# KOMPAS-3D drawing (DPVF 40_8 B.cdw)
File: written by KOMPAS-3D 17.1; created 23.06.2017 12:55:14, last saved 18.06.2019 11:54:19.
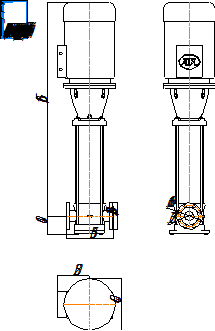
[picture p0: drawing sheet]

Sheet 1: A4, portrait

Title block, sheet 1: name: DPVF 40_8 B; material: Внимание! Данный продукт является объектом авторского права ООО «Торговый Дом АДЛ». / Запрещается изменение, копирование, распространение / (в том числе путем копирования на другие сайты и ресурсы в Интернете) / или любое иное использование информации и объектов без предварительного / согласия правообладателя (ООО «Торговый Дом АДЛ»).; scale: 1:1; sheets: 1; organisation: ООО "Торговый дом АДЛ"; sheet format: A4; stored path: C:\Клочков АВ\Насосы\DP PAMS\DPVF 40\Компас 2d\DPVF 40_8 B.cdw

Views: Спереди 1
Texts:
  Клочков АВ
  ООО АДЛ ГРУПП
Dimensions and other numbers on the sheet: 365; 250; 400; 209,6; 1663,5; 140; 168,1; 76,2; 1:1; 1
